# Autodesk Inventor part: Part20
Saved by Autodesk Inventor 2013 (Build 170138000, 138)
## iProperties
Created: 2012-07
Part Number: Part20
Material: Generic
Document SubType Name: Modeling
Designer: Paul
Density: 1 g/cm^3
Author: Paul
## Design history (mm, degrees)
node "User Library-Arduino Mega.SAT1"
body "Solid1"
node "Base1"
